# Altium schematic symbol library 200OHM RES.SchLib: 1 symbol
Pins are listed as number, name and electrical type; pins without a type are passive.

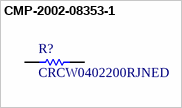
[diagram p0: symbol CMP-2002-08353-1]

## CMP-2002-08353-1
designator R?, comment CRCW0402200RJNED
Manufacturer: Vishay Dale
footprint RESC1005X40X25NL05T05 (Chip Resistor, 2-Leads, Body 1.00x0.50mm, IPC Medium Density)
footprint RESC1005X40X25ML05T05 (Chip Resistor, 2-Leads, Body 1.00x0.50mm, IPC Low Density)
footprint RESC1005X40X25LL05T05 (Chip Resistor, 2-Leads, Body 1.00x0.50mm, IPC High Density)
pins: 1, 2
1 alternate drawing of the same symbol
